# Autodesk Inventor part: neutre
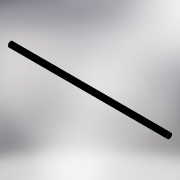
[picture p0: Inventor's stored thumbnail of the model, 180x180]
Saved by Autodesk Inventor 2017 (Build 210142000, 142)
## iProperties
Created: 2017-03
Part Number: neutre
Material: Generic
Document SubType Name: Modeling
Designer: thierry.jost
Density: 1 g/cm^3
Appearance: Anodized - Black
Author: thierry.jost
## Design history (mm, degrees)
sketch "Sketch1"
  geometry: C1 r 2.5 at (0, 0); 1 further point
  constraints: 1 centre point, 1 coincident
  dimensions: "d0" = 5 diameter of C1
extrude "Extrusion1" new body sketch "Sketch1" distance "d1" = 150; taper "d2" = 0 deg
body "Solid1"
